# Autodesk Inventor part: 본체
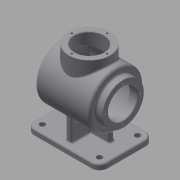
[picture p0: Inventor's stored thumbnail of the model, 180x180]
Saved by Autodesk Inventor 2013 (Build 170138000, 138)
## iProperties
Created: 2016-09
Part Number: 본체
Material: 일반
Document SubType Name: Modeling
Designer: Administrator
Density: 1 g/cm^3
Author: Administrator
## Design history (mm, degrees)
sketch "스케치1"
  geometry: L1 (-67.5, 50)-(67.5, 50); L2 (67.5, 50)-(67.5, -50); L3 (67.5, -50)-(-67.5, -50); L4 (-67.5, -50)-(-67.5, 50); L5 (67.5, -50)-(-67.5, 50); 2 further points
  constraints: 10 end point, 2 parallel, 1 coincident, 1 horizontal, 1 midpoint, 1 perpendicular
  dimensions: "d0" = 135 distance of L1.start L1.end; "d2" = 100 distance of L1.end L2.end
extrude "돌출1" new body sketch "스케치1" distance "d3" = 10; taper "d4" = 0 deg
fillet "모깎기1" dims "d5" = 15
fillet "모깎기2" dims "d6" = 3
hole "구멍1" diameter "d9" = 10; stored, may be unused: countersink angle "d13" = 90 deg, drill point angle "d15" = 0 deg; dims "d7" = 10, "d8" = 10, "d10" = 6, "d11" = 4, "d12" = 2, "d14" = 8
hole "구멍2" diameter "d18" = 10; stored, may be unused: countersink angle "d22" = 90 deg, drill point angle "d24" = 0 deg; dims "d16" = 10, "d17" = 10, "d19" = 6, "d20" = 4, "d21" = 2, "d23" = 8
hole "구멍3" diameter "d27" = 10; stored, may be unused: countersink angle "d31" = 90 deg, drill point angle "d33" = 0 deg; dims "d25" = 10, "d26" = 10, "d28" = 6, "d29" = 4, "d30" = 2, "d32" = 8
hole "구멍4" diameter "d36" = 10; stored, may be unused: countersink angle "d40" = 90 deg, drill point angle "d42" = 0 deg; dims "d34" = 10, "d35" = 10, "d37" = 6, "d38" = 4, "d39" = 2, "d41" = 8
sketch "스케치2"
  geometry: L1 (-52.5, 0)-(52.5, 0) reference; L2 (0, 0)-(0, 82); L3 (-61, 82)-(61, 82); L4 (-61, 82)-(-61, 120); L5 (-61, 120)-(-49, 120); L6 (-49, 120)-(-49, 132); L7 (-49, 132)-(49.562, 132); A1 r 115 centre (-54, 82) between (61, 82) and (49.562, 132)
  constraints: 12 end point, 6 perpendicular, 2 point on circle, 1 centre point, 1 midpoint
  dimensions: "d43" = 82 distance of L2.end L2.start; "d44" = 122 distance of L3.start L3.end; "d45" = 12 distance of L4.end L5.end; "d46" = 110 distance edge to line of A1 L6; "d47" = 115 radius of A1; "d48" = 76 diameter of L5 L3; "d49" = 100 diameter of L7 L3
revolve "회전1" sketch "스케치2" stored, may be unused: angle "d50" = 90 deg
node "작업 평면1"
sketch "스케치3"
  geometry: L1 (61, 38)-(61, -38) reference; L2 (61, 0)-(-1, 0); C1 r 38 at (-1, 0); 1 further point
  constraints: 2 end point, 1 centre point, 1 coincident, 1 midpoint, 1 perpendicular
  dimensions: "d52" = 62 distance of L2.start L2.end; "d54" = 76 diameter of C1
extrude "돌출2" join sketch "스케치3" stored distance "d55" = 10; taper "d56" = 0 deg
sketch "스케치4"
  geometry: L1 (-61, 44)-(-61, 120) reference; L2 (-61, 120)-(-49, 120) reference; L3 (-49, 120)-(-49, 132) reference; L4 (-49, 132)-(-37, 132) reference; L5 (-37, 132)-(-37, 147) reference; L6 (-37, 147)-(39, 147) reference; L7 (39, 147)-(39, 132) reference; L8 (39, 132)-(49.562, 132) reference; L9 (49.562, 32)-(-49, 32) reference; L10 (-49, 32)-(-49, 44) reference; L11 (-49, 44)-(-61, 44) reference; L12 (-67.5, 0)-(-67.5, 7) reference; L13 (-64.5, 10)-(64.5, 10) reference; L14 (67.5, 7)-(67.5, 0) reference; L15 (67.5, 0)-(-67.5, 0) reference; L16 (-61, 82)-(61, 82); L17 (47.661, 129)-(26.333, 129); L18 (-9.833, 129)-(-46, 129); L19 (-46, 129)-(-46, 117); L20 (26.333, 129)-(-9.833, 129); L21 (-46, 117)-(-46, 82); A1 r 115 centre (-54, 82) between (49.562, 32) and (49.562, 132) reference; A2 r 3 centre (-64.5, 7) between (-64.5, 10) and (-67.5, 7) reference; A3 r 3 centre (64.5, 7) between (67.5, 7) and (64.5, 10) reference; A4 r 112 centre (-54, 82) between (58, 82) and (47.661, 129); 1 further point
  constraints: 12 end point, 3 point on circle, 2 collinear, 2 point on line, 1 centre point, 1 midpoint, 1 perpendicular, 1 other
  dimensions: "d57" = 3 radial gap between concentric circles of A1 A4; "d59" = 3 distance between parallel lines of L17 L8
revolve "회전2" sketch "스케치4" stored, may be unused: angle "d60" = 90 deg
hole "구멍5" diameter "d63" = 54; stored, may be unused: countersink angle "d67" = 90 deg, drill point angle "d69" = 0 deg; dims "d61" = 10, "d62" = 10, "d64" = 6, "d65" = 4, "d66" = 2, "d68" = 15
chamfer "모따기1" distance "d70" = 1; stored, may be unused: second distance "d71" = 2, angle "d72" = 45 deg
fillet "모깎기3" dims "d73" = 5
fillet "모깎기4" dims "d74" = 3
fillet "모깎기5" dims "d75" = 3
hole "구멍6" diameter "d78" = 54; stored, may be unused: countersink angle "d82" = 90 deg, drill point angle "d84" = 0 deg; dims "d76" = 10, "d77" = 10, "d79" = 6, "d80" = 4, "d81" = 2, "d83" = 54
chamfer "모따기2" distance "d85" = 1; stored, may be unused: second distance "d86" = 2, angle "d87" = 45 deg
fillet "모깎기6" dims "d88" = 2
sketch "스케치5" dims "d89" = 65
  geometry: L1 (0, 0)-(0, 32.5); C1 r 38 at (0, 0) reference; C2 r 28 at (0, 0) reference; 2 further points
  constraints: 2 coincident, 2 end point, 1 vertical, 1 vertical alignment, 2 other
hole "구멍7" sketch "스케치5" at (0, 32.5) diameter "d91" = 3.242; stored, may be unused: countersink angle "d95" = 90 deg, drill point angle "d97" = 118 deg; dims "d92" = 8, "d93" = 4, "d94" = 2, "d96" = 10
sketch "스케치6" dims "d101" = 65
  geometry: L1 (0, 0)-(0, 32.5); C1 r 38 at (0, 0) reference; C2 r 28 at (0, 0) reference; 2 further points
  constraints: 2 coincident, 2 end point, 1 vertical, 1 vertical alignment, 2 other
hole "구멍8" sketch "스케치6" at (0, 32.5) diameter "d103" = 3.242; stored, may be unused: countersink angle "d107" = 90 deg, drill point angle "d109" = 118 deg; dims "d104" = 8, "d105" = 4, "d106" = 2, "d108" = 10
sketch "스케치7"
  geometry: L1 (-52.5, 50)-(52.5, 50) reference; L2 (67.5, 35)-(67.5, -35) reference; L3 (52.5, -50)-(-52.5, -50) reference; L4 (-67.5, -35)-(-67.5, 35) reference; L5 (0, 50)-(0, -50); L6 (-5, 40)-(5, 40); L7 (5, 40)-(5, -40); L8 (5, -40)-(-5, -40); L9 (-5, -40)-(-5, 40); L10 (5, -40)-(-5, 40); C1 r 5 at (52.5, -35) reference; C2 r 5 at (52.5, 35) reference; C3 r 5 at (-52.5, 35) reference; C4 r 5 at (-52.5, -35) reference; A1 r 15 centre (-52.5, 35) between (-52.5, 50) and (-67.5, 35) reference; A2 r 15 centre (52.5, 35) between (67.5, 35) and (52.5, 50) reference; A3 r 15 centre (52.5, -35) between (52.5, -50) and (67.5, -35) reference; A4 r 15 centre (-52.5, -35) between (-67.5, -35) and (-52.5, -50) reference; 2 further points
  constraints: 12 end point, 4 midpoint, 2 parallel, 1 horizontal, 1 perpendicular, 1 other
  dimensions: "d113" = 10 distance of L6.start L6.end; "d115" = 80 distance of L6.end L7.end
extrude "돌출3" join sketch "스케치7" stored distance "d116" = 10; taper "d117" = 0 deg
sketch "스케치8"
  geometry: L1 (-5, 10)-(-5, 52) reference; L2 (5, 10)-(5, 52) reference; L3 (-52.5, 10)-(52.5, 10) reference; L4 (-94.5, 147)-(94.5, 147) reference; L5 (-44, 32)-(46.374, 32) reference; L6 (-38.075, 32)-(-40, 10); L7 (38.075, 32)-(40, 10); L8 (0, 0)-(0, 24.389)
  constraints: 6 end point, 4 point on line, 1 perpendicular
  dimensions: "d118" = 40 distance from line of L6.end L8; "d120" = 95 deg angle of L3 L6; "d122" = 95 deg angle of L7 L3; "d124" = 40 distance from line of L7.end L8
feature "리브1" dims "d125" = 1, "d126" = 10, "d127" = 0, "d128" = 0, "d129" = 1, "d130" = 1
node "작업 평면3"
sketch "스케치9"
  geometry: L1 (-29.035, 4.203)-(29.035, 4.203); L2 (29.035, 4.203)-(29.035, -4.203); L3 (29.035, -4.203)-(-29.035, -4.203); L4 (-29.035, -4.203)-(-29.035, 4.203); L5 (-29.035, -4.203)-(29.035, 4.203); C1 r 47.045 at (0, 0) reference; 2 further points
  constraints: 2 end point, 1 coincident, 1 midpoint, 2 other
feature "엠보싱1" sketch "스케치9" dims "d9" = 10, "d11" = 4, "d12" = 2, "d14" = 8, "d131" = 0.5, "d132" = 0
fillet "모깎기7" dims "d133" = 3
fillet "모깎기8" dims "d134" = 3
fillet "모깎기9" dims "d135" = 3
node "솔리드1"
pattern_circular "원형 패턴1" dims angle "d99" = 360 deg
pattern_circular "원형 패턴2" dims angle "d111" = 360 deg
mirror "대칭1"
node "투영된 루프1"
node "투영된 루프2"
node "투영된 루프3"
node "작업 평면2"
node "투영된 루프4"
node "절단 모서리 투영1"
other parameters: "d51" = 147
